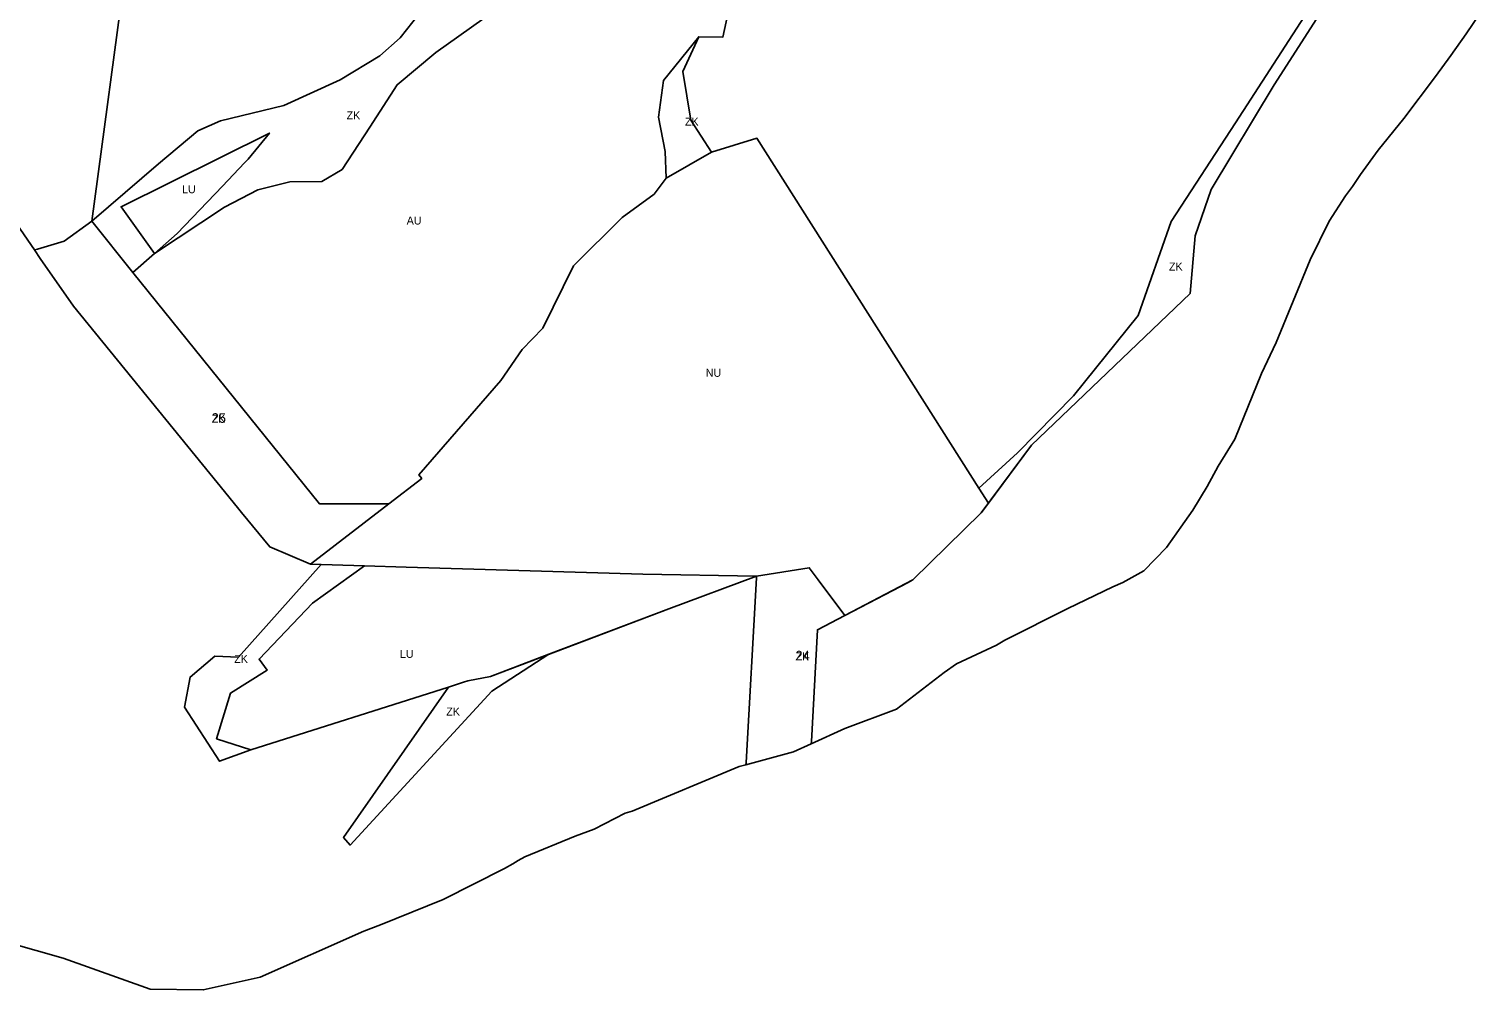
# Model space of a CAD drawing. Extents: x -541351 to -537540, y -1162694 to -1159725.
# Drawn here: x -538734 to -537827, y -1162694 to -1162094 of the extents above; entities that cross this region are included whole.
import ezdxf

# ---------------------------------------------------------------- set-up
doc = ezdxf.new("R2010")
doc.units = 0
for name, color, linetype in [('90710013', 7, 'Continuous'), ('90710023', 7, 'Continuous'), ('90730013', 7, 'Continuous'), ('90730023', 7, 'Continuous'), ('90750013', 7, 'Continuous'), ('90770013', 7, 'Continuous'), ('90910012', 7, 'Continuous'), ('ID_navrh', 7, 'Continuous')]:
    doc.layers.add(name, color=color, linetype=linetype)

msp = doc.modelspace()

# ---------------------------------------------------------------- linework, layer by layer
at = {"layer": '90710013'}
for points in [[(-538134.96, -1162390.143), (-538134.96, -1162390.143), (-538140.901, -1162380.777), (-538140.901, -1162380.777), (-538116.81, -1162358.63), (-538081.87, -1162323), (-538041.52, -1162272.9), (-538020.92, -1162214.26), (-537980.73, -1162152.69), (-537959.1, -1162119.55), (-537913.59, -1162048.98), (-537903.511, -1162046.433), (-537956.408, -1162128.79), (-537995.859, -1162194.216), (-538005.857, -1162223.144), (-538008.924, -1162259.128), (-538108.15, -1162353.88)], [(-538307.92, -1162170.92), (-538336.366, -1162187.229), (-538336.958, -1162170.513), (-538341.127, -1162149.039), (-538337.885, -1162126.175), (-538315.9, -1162098.85), (-538325.79, -1162120.61), (-538320.79, -1162150.88)], [(-538551.73, -1162428.455), (-538524.77, -1162429.273), (-538557.2, -1162452.57), (-538590.57, -1162487.53), (-538585.52, -1162494.51), (-538608.47, -1162508.72), (-538617.07, -1162537.21), (-538595.65, -1162544.21), (-538615.309, -1162551.339), (-538637.149, -1162517.604), (-538633.701, -1162498.724), (-538618.279, -1162485.594), (-538603.432, -1162486.36)], [(-538537.771, -1162598.966), (-538472.23, -1162504.99), (-538462.84, -1162502), (-538460.21, -1162501.17), (-538445.95, -1162498.39), (-538409.51, -1162484.527), (-538445.136, -1162507.643), (-538533.742, -1162603.671)]]:
    msp.add_lwpolyline(points, close=True, dxfattribs=at)
msp.add_lwpolyline([(-538443.532, -1162082.673), (-538480.243, -1162108.669), (-538504.214, -1162128.795), (-538521.479, -1162155.294), (-538538.745, -1162181.794), (-538551.317, -1162189.174), (-538571.265, -1162189.341), (-538591.38, -1162194.373), (-538612.167, -1162205.274), (-538655.83, -1162234.14), (-538641.65, -1162221.7), (-538613.46, -1162192.15), (-538599.58, -1162177.6), (-538597.29, -1162175.19), (-538584.08, -1162158.95), (-538676.75, -1162205), (-538655.83, -1162234.14), (-538669.344, -1162245.986), (-538695.05, -1162214.09), (-538695.05, -1162214.09), (-538653.403, -1162178.176), (-538628.881, -1162157.667), (-538614.681, -1162151.245), (-538575.121, -1162141.853), (-538539.919, -1162125.752), (-538515.11, -1162110.825), (-538502.37, -1162099.588), (-538490.468, -1162084.494)], dxfattribs=at)
at = {"layer": '90710023'}
for points in [[(-538730.919, -1162231.96), (-538729.02, -1162231.4), (-538712.27, -1162226.46), (-538695.05, -1162214.09), (-538669.344, -1162245.986), (-538552.876, -1162390.495), (-538509.498, -1162390.495), (-538558.466, -1162428.25), (-538583.87, -1162417.45), (-538601.47, -1162395.9), (-538603.16, -1162393.83), (-538612.14, -1162382.82), (-538706.58, -1162267.12), (-538727.27, -1162237.23)], [(-538279.881, -1162436.731), (-538279.83, -1162435.82), (-538246.94, -1162430.44), (-538241.328, -1162437.916), (-538224.597, -1162460.201), (-538241.787, -1162469.145), (-538245.569, -1162539.032), (-538245.642, -1162540.385), (-538256.67, -1162545.39), (-538286.407, -1162553.479), (-538286.333, -1162552.153)]]:
    msp.add_lwpolyline(points, close=True, dxfattribs=at)
at = {"layer": '90730013'}
msp.add_lwpolyline([(-538498.605, -1162430.067), (-538524.77, -1162429.273), (-538558.466, -1162428.25), (-538509.498, -1162390.495), (-538488.91, -1162374.62), (-538490.74, -1162372.39), (-538439.64, -1162313.45), (-538426.13, -1162294.07), (-538413.32, -1162280.83), (-538394.221, -1162241.992), (-538363.687, -1162211.712), (-538343.691, -1162197.113), (-538336.366, -1162187.229), (-538307.92, -1162170.92), (-538279.54, -1162162.191), (-538140.901, -1162380.777), (-538134.96, -1162390.143), (-538139.442, -1162396.204), (-538182.135, -1162438.109), (-538185.086, -1162439.644), (-538224.597, -1162460.201), (-538241.328, -1162437.916), (-538246.94, -1162430.44), (-538279.83, -1162435.82), (-538350.838, -1162434.55)], close=True, dxfattribs=at)
at = {"layer": '90730023'}
msp.add_lwpolyline([(-538713.86, -1162034.77), (-538672.267, -1162044.823), (-538673.105, -1162051.048), (-538695.05, -1162214.09), (-538712.27, -1162226.46), (-538729.02, -1162231.4), (-538730.919, -1162231.96), (-538766.94, -1162179.94), (-538768.78, -1162182.83), (-538771.26, -1162186.72), (-538773.11, -1162183.87), (-538866.22, -1162040.39), (-538863.08, -1162039.76), (-538826.9, -1162032.51), (-538822.45, -1162030.47), (-538816.04, -1162027.52), (-538804.26, -1162018.41), (-538803.58, -1162020.1), (-538796.41, -1162018.51), (-538772.02, -1162020.88)], close=True, dxfattribs=at)
at = {"layer": '90750013'}
for points in [[(-537827.3, -1162083.56), (-537836.59, -1162097.02), (-537846.19, -1162110.58), (-537855.72, -1162123.63), (-537875.49, -1162149.88), (-537891.57, -1162169.65), (-537902.65, -1162184.82), (-537907.5, -1162192.31), (-537911.86, -1162198.11), (-537922.18, -1162213.99), (-537933.96, -1162238.09), (-537955.18, -1162289.88), (-537964.3, -1162309.05), (-537981.13, -1162350.15), (-537991.36, -1162367.12), (-537998.23, -1162379.68), (-538007.3, -1162394.44), (-538023.79, -1162417.82), (-538037.95, -1162432.29), (-538051.04, -1162439.71), (-538057.18, -1162442.45), (-538085.43, -1162455.94), (-538124.67, -1162475.77), (-538129.94, -1162478.83), (-538154.81, -1162490.46), (-538162.69, -1162495.9), (-538192.39, -1162518.69), (-538224.57, -1162530.82), (-538245.642, -1162540.385), (-538245.569, -1162539.032), (-538241.787, -1162469.145), (-538224.597, -1162460.201), (-538224.597, -1162460.201), (-538182.135, -1162438.109), (-538139.442, -1162396.204), (-538108.15, -1162353.88), (-538008.924, -1162259.128), (-538005.857, -1162223.144), (-537995.859, -1162194.216), (-537956.408, -1162128.79), (-537903.511, -1162046.433)], [(-538490.468, -1162084.494), (-538502.37, -1162099.588), (-538515.11, -1162110.825), (-538539.919, -1162125.752), (-538575.121, -1162141.853), (-538614.681, -1162151.245), (-538628.881, -1162157.667), (-538653.403, -1162178.176), (-538695.05, -1162214.09), (-538695.05, -1162214.09), (-538673.105, -1162051.048)], [(-538294.68, -1162070.18), (-538300.82, -1162098.99), (-538315.9, -1162098.85), (-538315.9, -1162098.85), (-538337.885, -1162126.175), (-538341.127, -1162149.039), (-538336.958, -1162170.513), (-538336.366, -1162187.229), (-538343.691, -1162197.113), (-538363.687, -1162211.712), (-538394.221, -1162241.992), (-538413.32, -1162280.83), (-538426.13, -1162294.07), (-538439.64, -1162313.45), (-538490.74, -1162372.39), (-538490.74, -1162372.39), (-538488.91, -1162374.62), (-538488.91, -1162374.62), (-538509.498, -1162390.495), (-538552.876, -1162390.495), (-538669.344, -1162245.986), (-538655.83, -1162234.14), (-538655.83, -1162234.14), (-538612.167, -1162205.274), (-538591.38, -1162194.373), (-538571.265, -1162189.341), (-538551.317, -1162189.174), (-538538.745, -1162181.794), (-538521.479, -1162155.294), (-538504.214, -1162128.795), (-538480.243, -1162108.669), (-538443.532, -1162082.673)], [(-538766.94, -1162179.94), (-538730.919, -1162231.96), (-538727.27, -1162237.23), (-538706.58, -1162267.12), (-538612.14, -1162382.82), (-538603.16, -1162393.83), (-538601.47, -1162395.9), (-538583.87, -1162417.45), (-538558.466, -1162428.25), (-538551.73, -1162428.455), (-538603.432, -1162486.36), (-538618.279, -1162485.594), (-538633.701, -1162498.724), (-538637.149, -1162517.604), (-538615.309, -1162551.339), (-538595.65, -1162544.21), (-538472.23, -1162504.99), (-538537.771, -1162598.966), (-538533.742, -1162603.671), (-538445.136, -1162507.643), (-538409.51, -1162484.527), (-538409.51, -1162484.527), (-538334.63, -1162456.04), (-538279.83, -1162435.82), (-538279.881, -1162436.731), (-538286.333, -1162552.153), (-538286.407, -1162553.479), (-538290.71, -1162554.65), (-538357.43, -1162582.44), (-538361.85, -1162583.75), (-538381.21, -1162593.74), (-538393.08, -1162598.16), (-538424.63, -1162610.94), (-538428.73, -1162613.36), (-538432.09, -1162615.33), (-538437.2, -1162618.34), (-538475.64, -1162637.57), (-538514.72, -1162653.42), (-538525.11, -1162657.36), (-538589.99, -1162686.16), (-538625.49, -1162694.15), (-538658.52, -1162693.62), (-538712.88, -1162674.25), (-538779.19, -1162655.51)]]:
    msp.add_lwpolyline(points, dxfattribs=at)
at = {"layer": '90770013'}
msp.add_lwpolyline([(-537913.59, -1162048.98), (-537959.1, -1162119.55), (-537980.73, -1162152.69), (-538020.92, -1162214.26), (-538041.52, -1162272.9), (-538081.87, -1162323), (-538116.81, -1162358.63), (-538140.901, -1162380.777), (-538279.54, -1162162.191), (-538307.92, -1162170.92), (-538320.79, -1162150.88), (-538325.79, -1162120.61), (-538315.9, -1162098.85), (-538300.82, -1162098.99), (-538294.68, -1162070.18)], dxfattribs=at)
for points in [[(-538597.29, -1162175.19), (-538599.58, -1162177.6), (-538613.46, -1162192.15), (-538641.65, -1162221.7), (-538655.83, -1162234.14), (-538676.75, -1162205), (-538584.08, -1162158.95)], [(-538557.2, -1162452.57), (-538524.77, -1162429.273), (-538498.605, -1162430.067), (-538350.838, -1162434.55), (-538279.83, -1162435.82), (-538334.63, -1162456.04), (-538445.95, -1162498.39), (-538460.21, -1162501.17), (-538462.84, -1162502), (-538472.23, -1162504.99), (-538595.65, -1162544.21), (-538617.07, -1162537.21), (-538608.47, -1162508.72), (-538587.16, -1162495.52), (-538585.52, -1162494.51), (-538590.57, -1162487.53)]]:
    msp.add_lwpolyline(points, close=True, dxfattribs=at)
at = {"layer": '90910012'}
msp.add_lwpolyline([(-538695.05, -1162214.09), (-538669.344, -1162245.986)], dxfattribs=at)

# ---------------------------------------------------------------- texts
at = {"layer": '90710013'}
for rotation, p in [(0, (-538535.918, -1162150.399)), (0, (-538324.524, -1162154.358)), (360, (-538022.206, -1162244.866)), (0, (-538606.095, -1162489.897)), (360, (-538473.641, -1162522.774))]:
    msp.add_text('ZK', height=5, rotation=rotation, dxfattribs=at).set_placement(p)
at = {"layer": '90710023'}
for p in [(-538620.209, -1162339.943), (-538255.502, -1162488.35)]:
    msp.add_text('ZK', height=5, rotation=0, dxfattribs=at).set_placement(p)
at = {"layer": '90730013'}
msp.add_text('NU', height=5, rotation=0, dxfattribs=at).set_placement((-538311.551, -1162311.196))
at = {"layer": '90750013'}
msp.add_text('AU', height=5, rotation=0, dxfattribs=at).set_placement((-538498.361, -1162216.127))
at = {"layer": '90770013'}
for p in [(-538638.694, -1162196.545), (-538502.574, -1162486.741)]:
    msp.add_text('LU', height=5, rotation=360, dxfattribs=at).set_placement(p)
at = {"layer": 'ID_navrh'}
for s, p in [('25', (-538620.209, -1162339.943)), ('24', (-538255.502, -1162488.35))]:
    msp.add_text(s, height=6, rotation=0, dxfattribs=at).set_placement(p)

doc.saveas('drawing.dxf')
